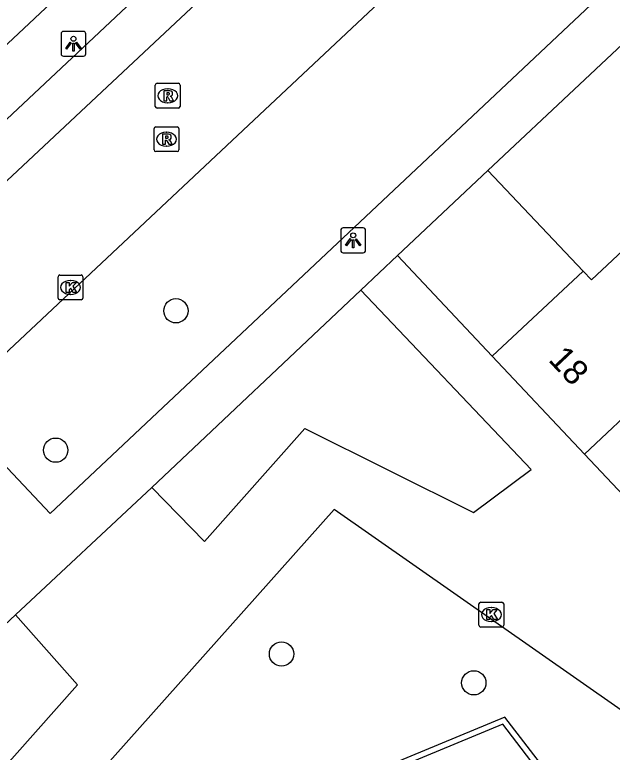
# Model space of a CAD drawing. Extents: x 162542 to 163144, y 380786 to 381511.
# Drawn here: x 162648.14 to 162672.18, y 381201.72 to 381231.41 of the extents above; entities that cross this region are included whole.
import ezdxf

# ---------------------------------------------------------------- set-up
doc = ezdxf.new("R2010")
doc.units = 0
for name, color, linetype in [('IMGEO_Boom', 7, 'Continuous'), ('IMGEO_Kolk', 7, 'Continuous'), ('IMGEO_Lichtpunt', 7, 'Continuous'), ('IMGEO_Muur', 7, 'Continuous'), ('IMGEO_Pand', 7, 'Continuous'), ('IMGEO_Pand_nummerreeks', 7, 'Continuous'), ('IMGEO_Rijbaan_lokaal_open', 7, 'Continuous'), ('IMGEO_Rioolput', 7, 'Continuous'), ('IMGEO_Voetpad_open', 7, 'Continuous')]:
    doc.layers.add(name, color=color, linetype=linetype)

msp = doc.modelspace()

# ---------------------------------------------------------------- linework, layer by layer
at = {"layer": 'IMGEO_Boom'}
for centre in [(162654.621, 381219.495), (162649.785, 381213.885), (162658.87, 381205.681), (162666.606, 381204.519)]:
    msp.add_circle(centre, 0.489, dxfattribs=at)
at = {"layer": 'IMGEO_Kolk'}
for p, q in [((162649.88, 381220.01), (162649.88, 381220.862)), ((162649.955, 381220.936), (162650.807, 381220.936)), ((162650.881, 381220.862), (162650.881, 381220.01)), ((162650.368, 381220.716), (162650.393, 381220.716)), ((162650.391, 381220.156), (162650.366, 381220.156)), ((162650.807, 381219.936), (162649.955, 381219.936)), ((162666.813, 381206.84), (162666.813, 381207.692)), ((162666.888, 381207.766), (162667.74, 381207.766)), ((162667.301, 381207.546), (162667.326, 381207.546)), ((162667.814, 381207.692), (162667.814, 381206.84)), ((162667.324, 381206.986), (162667.299, 381206.986)), ((162667.74, 381206.766), (162666.888, 381206.766))]:
    msp.add_line(p, q, dxfattribs=at)
for points in [[(162649.88, 381220.01), (162649.88, 381220.862)], [(162649.955, 381220.936), (162650.807, 381220.936)], [(162650.881, 381220.862), (162650.881, 381220.01)], [(162650.201, 381220.636), (162650.324, 381220.636), (162650.324, 381220.485), (162650.454, 381220.636), (162650.618, 381220.636), (162650.472, 381220.485), (162650.625, 381220.236), (162650.473, 381220.236), (162650.388, 381220.4), (162650.324, 381220.333), (162650.324, 381220.236), (162650.201, 381220.236), (162650.201, 381220.636)], [(162650.807, 381219.936), (162649.955, 381219.936)], [(162666.813, 381206.84), (162666.813, 381207.692)], [(162666.888, 381207.766), (162667.74, 381207.766)], [(162667.814, 381207.692), (162667.814, 381206.84)], [(162667.134, 381207.466), (162667.257, 381207.466), (162667.257, 381207.315), (162667.387, 381207.466), (162667.551, 381207.466), (162667.405, 381207.315), (162667.558, 381207.066), (162667.406, 381207.066), (162667.321, 381207.23), (162667.257, 381207.163), (162667.257, 381207.066), (162667.134, 381207.066), (162667.134, 381207.466)], [(162667.74, 381206.766), (162666.888, 381206.766)]]:
    msp.add_lwpolyline(points, dxfattribs=at)
for centre, start, end in [((162649.957, 381220.86), 91.552, 178.448), ((162649.957, 381220.86), 91.552, 178.448), ((162650.805, 381220.86), 1.552, 88.448), ((162650.805, 381220.86), 1.552, 88.448), ((162649.957, 381220.012), 181.552, 268.448), ((162649.957, 381220.012), 181.552, 268.448), ((162650.805, 381220.012), 271.552, 358.448), ((162650.805, 381220.012), 271.552, 358.448), ((162666.89, 381207.69), 91.552, 178.448), ((162666.89, 381207.69), 91.552, 178.448), ((162667.738, 381207.69), 1.552, 88.448), ((162667.738, 381207.69), 1.552, 88.448), ((162666.89, 381206.842), 181.552, 268.448), ((162666.89, 381206.842), 181.552, 268.448), ((162667.738, 381206.842), 271.552, 358.448), ((162667.738, 381206.842), 271.552, 358.448)]:
    msp.add_arc(centre, 0.0765, start, end, dxfattribs=at)
for centre, major_axis, ratio, start_param, end_param in [((162650.367, 381220.436), (-0.387, 0.002), 0.722429, 4.712389, 7.853982), ((162650.392, 381220.436), (-0.39, 0.002), 0.717154, 1.570796, 4.712389), ((162667.3, 381207.266), (-0.387, 0.002), 0.722429, 4.712389, 7.853982), ((162667.325, 381207.266), (-0.39, 0.002), 0.717154, 1.570796, 4.712389)]:
    msp.add_ellipse(centre, major_axis=major_axis, ratio=ratio, start_param=start_param, end_param=end_param, dxfattribs=at)
at = {"layer": 'IMGEO_Lichtpunt'}
for p, q in [((162649.999, 381230.648), (162649.999, 381229.841)), ((162649.999, 381230.648), (162649.999, 381229.841)), ((162650.901, 381230.743), (162650.093, 381230.743)), ((162650.901, 381230.743), (162650.093, 381230.743)), ((162650.995, 381229.841), (162650.995, 381230.648)), ((162650.995, 381229.841), (162650.995, 381230.648)), ((162650.093, 381229.747), (162650.901, 381229.747)), ((162650.093, 381229.747), (162650.901, 381229.747)), ((162661.255, 381222.735), (162661.255, 381221.928)), ((162661.255, 381222.735), (162661.255, 381221.928)), ((162662.157, 381222.83), (162661.349, 381222.83)), ((162662.157, 381222.83), (162661.349, 381222.83)), ((162662.251, 381221.928), (162662.251, 381222.735)), ((162662.251, 381221.928), (162662.251, 381222.735)), ((162661.349, 381221.834), (162662.157, 381221.834)), ((162661.349, 381221.834), (162662.157, 381221.834))]:
    msp.add_line(p, q, dxfattribs=at)
for points in [[(162650.373, 381230.312), (162650.412, 381230.284), (162650.224, 381230.022), (162650.186, 381230.049), (162650.373, 381230.312)], [(162650.475, 381230.264), (162650.522, 381230.264), (162650.522, 381229.942), (162650.475, 381229.942), (162650.475, 381230.264)], [(162650.585, 381230.284), (162650.623, 381230.311), (162650.81, 381230.049), (162650.771, 381230.021), (162650.585, 381230.284)], [(162661.629, 381222.399), (162661.668, 381222.371), (162661.48, 381222.109), (162661.442, 381222.136), (162661.629, 381222.399)], [(162661.731, 381222.351), (162661.778, 381222.351), (162661.778, 381222.029), (162661.731, 381222.029), (162661.731, 381222.351)], [(162661.841, 381222.371), (162661.879, 381222.398), (162662.066, 381222.136), (162662.027, 381222.108), (162661.841, 381222.371)]]:
    msp.add_lwpolyline(points, dxfattribs=at)
for centre in [(162650.498, 381230.446), (162661.754, 381222.533)]:
    msp.add_circle(centre, 0.0994, dxfattribs=at)
for centre, start, end in [((162650.093, 381230.648), 90, 180), ((162650.093, 381230.648), 90, 180), ((162650.901, 381230.648), 0, 90), ((162650.901, 381230.648), 0, 90), ((162650.093, 381229.841), 180, 270), ((162650.093, 381229.841), 180, 270), ((162650.901, 381229.841), 270, 0), ((162650.901, 381229.841), 270, 360), ((162661.349, 381222.735), 90, 180), ((162661.349, 381222.735), 90, 180), ((162662.157, 381222.735), 0, 90), ((162662.157, 381222.735), 0, 90), ((162661.349, 381221.928), 180, 270), ((162661.349, 381221.928), 180, 270), ((162662.157, 381221.928), 270, 0), ((162662.157, 381221.928), 270, 360)]:
    msp.add_arc(centre, 0.0946, start, end, dxfattribs=at)
at = {"layer": 'IMGEO_Muur'}
for points in [[(162677.867, 381189.622), (162678.101, 381189.825), (162667.855, 381203.134), (162649.886, 381195.669)], [(162677.867, 381189.622), (162667.775, 381202.852), (162649.968, 381195.455)]]:
    msp.add_lwpolyline(points, dxfattribs=at)
at = {"layer": 'IMGEO_Pand'}
for points in [[(162651.086, 381233.308), (162646.772, 381229.246), (162644.701, 381231.443), (162639.885, 381236.552)], [(162667.173, 381225.141), (162678.234, 381235.545)], [(162667.173, 381225.141), (162671.008, 381221.097)], [(162675.132, 381224.298), (162671.346, 381220.74), (162671.008, 381221.097)], [(162671.008, 381221.097), (162667.349, 381217.669)], [(162678.497, 381220.727), (162671.062, 381213.723)], [(162667.349, 381217.669), (162671.062, 381213.723)], [(162671.062, 381213.723), (162675.077, 381209.457)]]:
    msp.add_lwpolyline(points, dxfattribs=at)
at = {"layer": 'IMGEO_Rijbaan_lokaal_open'}
for points in [[(162662.218, 381238.238), (162631.935, 381209.859), (162631.308, 381209.256)], [(162666.064, 381234.987), (162664.548, 381233.561), (162645.49, 381215.653)]]:
    msp.add_lwpolyline(points, dxfattribs=at)
at = {"layer": 'IMGEO_Rioolput'}
for p, q in [((162653.792, 381227.726), (162653.792, 381228.578)), ((162653.867, 381228.652), (162654.719, 381228.652)), ((162654.793, 381228.578), (162654.793, 381227.726)), ((162654.28, 381228.432), (162654.305, 381228.432)), ((162654.303, 381227.872), (162654.278, 381227.872)), ((162654.719, 381227.652), (162653.867, 381227.652)), ((162653.74, 381225.976), (162653.74, 381226.828)), ((162653.815, 381226.902), (162654.667, 381226.902)), ((162654.741, 381226.828), (162654.741, 381225.976)), ((162654.228, 381226.682), (162654.253, 381226.682)), ((162654.667, 381225.902), (162653.815, 381225.902)), ((162654.251, 381226.122), (162654.226, 381226.122))]:
    msp.add_line(p, q, dxfattribs=at)
for points in [[(162653.792, 381227.726), (162653.792, 381228.578)], [(162653.867, 381228.652), (162654.719, 381228.652)], [(162654.793, 381228.578), (162654.793, 381227.726)], [(162654.381, 381228.35), (162654.129, 381228.352), (162654.129, 381227.952)], [(162654.307, 381228.271), (162654.253, 381228.271), (162654.253, 381228.19)], [(162654.129, 381227.952), (162654.253, 381227.952), (162654.253, 381228.114), (162654.264, 381228.114)], [(162654.253, 381228.19), (162654.305, 381228.19)], [(162654.311, 381228.085), (162654.382, 381227.952), (162654.522, 381227.952), (162654.457, 381228.078)], [(162654.719, 381227.652), (162653.867, 381227.652)], [(162653.74, 381225.976), (162653.74, 381226.828)], [(162653.815, 381226.902), (162654.667, 381226.902)], [(162654.741, 381226.828), (162654.741, 381225.976)], [(162654.329, 381226.6), (162654.077, 381226.602), (162654.077, 381226.202)], [(162654.255, 381226.521), (162654.201, 381226.521), (162654.201, 381226.44)], [(162654.077, 381226.202), (162654.201, 381226.202), (162654.201, 381226.364), (162654.212, 381226.364)], [(162654.201, 381226.44), (162654.253, 381226.44)], [(162654.259, 381226.335), (162654.33, 381226.202), (162654.47, 381226.202), (162654.405, 381226.328)], [(162654.667, 381225.902), (162653.815, 381225.902)]]:
    msp.add_lwpolyline(points, dxfattribs=at)
for centre, radius, start, end in [((162653.869, 381228.576), 0.0765, 91.552, 178.448), ((162653.869, 381228.576), 0.0765, 91.552, 178.448), ((162654.717, 381228.576), 0.0765, 1.552, 88.448), ((162654.717, 381228.576), 0.0765, 1.552, 88.448), ((162654.313, 381228.175), 0.0964, 77.0061, 93.1865), ((162654.327, 381228.232), 0.0378, 276.6634, 79.6772), ((162654.38, 381228.24), 0.109, 350.3612, 89.416), ((162654.263, 381228.061), 0.0533, 26.0293, 88.6989), ((162654.289, 381228.379), 0.19, 274.7715, 282.9687), ((162654.378, 381228.24), 0.112, 277.5842, 350.9817), ((162654.362, 381228.025), 0.108, 29.5134, 73.7905), ((162653.869, 381227.728), 0.0765, 181.552, 268.448), ((162653.869, 381227.728), 0.0765, 181.552, 268.448), ((162654.717, 381227.728), 0.0765, 271.552, 358.448), ((162654.717, 381227.728), 0.0765, 271.552, 358.448), ((162653.817, 381226.826), 0.0765, 91.552, 178.448), ((162653.817, 381226.826), 0.0765, 91.552, 178.448), ((162654.665, 381226.826), 0.0765, 1.552, 88.448), ((162654.665, 381226.826), 0.0765, 1.552, 88.448), ((162654.261, 381226.425), 0.0964, 77.0061, 93.1865), ((162654.275, 381226.482), 0.0378, 276.6634, 79.6772), ((162654.328, 381226.49), 0.109, 350.3612, 89.416), ((162654.211, 381226.311), 0.0533, 26.0293, 88.6989), ((162654.237, 381226.629), 0.19, 274.7715, 282.9687), ((162654.326, 381226.49), 0.112, 277.5842, 350.9817), ((162654.31, 381226.275), 0.108, 29.5134, 73.7905), ((162653.817, 381225.978), 0.0765, 181.552, 268.448), ((162653.817, 381225.978), 0.0765, 181.552, 268.448), ((162654.665, 381225.978), 0.0765, 271.552, 358.448), ((162654.665, 381225.978), 0.0765, 271.552, 358.448)]:
    msp.add_arc(centre, radius, start, end, dxfattribs=at)
for centre, major_axis, ratio, start_param, end_param in [((162654.279, 381228.152), (-0.387, 0.002), 0.722429, 4.712389, 7.853982), ((162654.304, 381228.152), (-0.39, 0.002), 0.717154, 1.570796, 4.712389), ((162654.227, 381226.402), (-0.387, 0.002), 0.722429, 4.712389, 7.853982), ((162654.252, 381226.402), (-0.39, 0.002), 0.717154, 1.570796, 4.712389)]:
    msp.add_ellipse(centre, major_axis=major_axis, ratio=ratio, start_param=start_param, end_param=end_param, dxfattribs=at)
at = {"layer": 'IMGEO_Voetpad_open'}
for points in [[(162630.092, 381210.576), (162660.951, 381239.561), (162662.218, 381238.238)], [(162668.885, 381237.638), (162672.906, 381233.335), (162649.563, 381211.338), (162645.49, 381215.653)], [(162663.537, 381221.72), (162667.173, 381225.141)], [(162662.06, 381220.329), (162663.537, 381221.72)], [(162663.537, 381221.72), (162667.349, 381217.669)], [(162653.658, 381212.378), (162662.06, 381220.329)], [(162653.658, 381212.378), (162655.776, 381210.209), (162659.812, 381214.758), (162666.594, 381211.38), (162668.918, 381213.104), (162662.06, 381220.329)], [(162648.167, 381207.261), (162653.658, 381212.378)], [(162688.758, 381192.072), (162660.986, 381211.497), (162648.992, 381198.027), (162649.886, 381195.669)], [(162643.831, 381180.07), (162638.909, 381198.566), (162648.167, 381207.261)], [(162653.633, 381182.688), (162643.156, 381195.983), (162650.664, 381204.44), (162648.167, 381207.261)]]:
    msp.add_lwpolyline(points, dxfattribs=at)

# ---------------------------------------------------------------- texts
at = {"layer": 'IMGEO_Pand_nummerreeks'}
msp.add_text('18', height=1, rotation=313.2581, dxfattribs=at).set_placement((162669.568, 381217.5))

doc.saveas('drawing.dxf')
